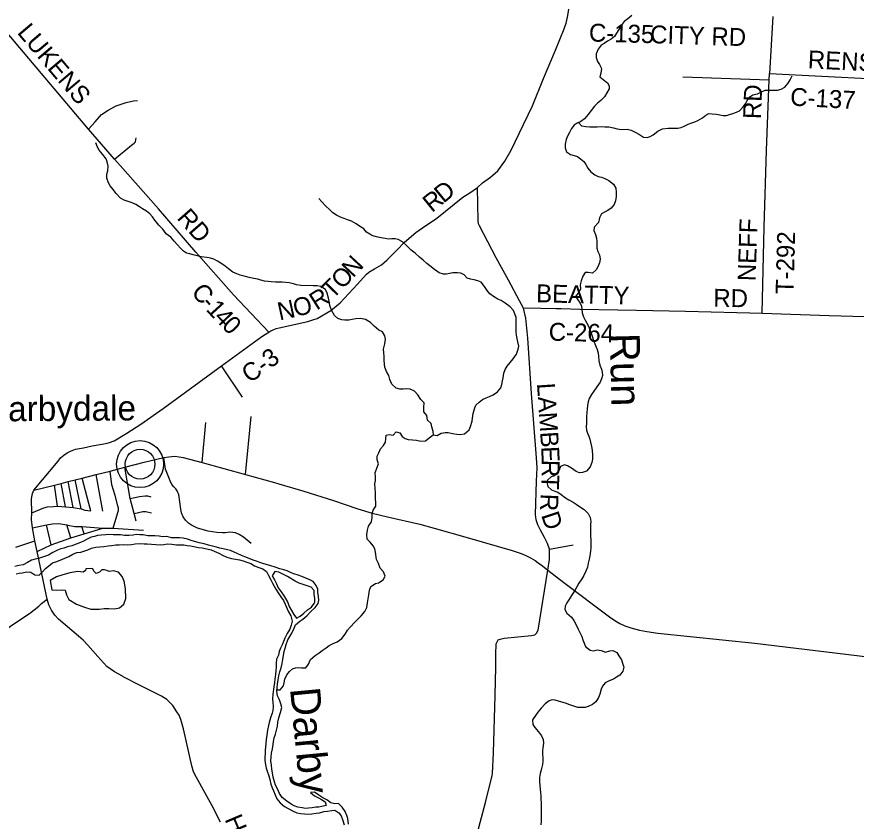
# Model space of a CAD drawing. Extents: x 114604 to 551442, y 316898 to 567001.
# Drawn here: x 152701 to 166736, y 341392 to 354850 of the extents above; entities that cross this region are included whole.
import ezdxf

# ---------------------------------------------------------------- set-up
doc = ezdxf.new("R2010")
doc.units = 0
for name, color, linetype in [('_CIVIL_CONSTRUCTION', 7, 'Continuous'), ('DV_X_County_Line', 7, 'Continuous'), ('GE_P_Alignment_1000_Cardinal_Points', 7, 'Continuous'), ('GE_P_Alignment_500_Bearings', 7, 'Continuous'), ('GE_X_Alignment', 7, 'Continuous'), ('MT_X_Edge_Line', 7, 'Continuous'), ('PM_P_Cells', 7, 'Continuous'), ('PM_P_CL_Double_Solid', 7, 'Continuous'), ('PM_P_Crosswalk', 7, 'Continuous'), ('PM_P_Stop_Line', 7, 'Continuous'), ('PM_X_Dotted_Line', 7, 'Continuous'), ('RD_P_GR_Rt', 7, 'Continuous')]:
    doc.layers.add(name, color=color, linetype=linetype)

msp = doc.modelspace()

# ---------------------------------------------------------------- linework, layer by layer
at = {"layer": '_CIVIL_CONSTRUCTION'}
msp.add_line((153001, 346082), (152964, 346298), dxfattribs=at)
for points in [[(152987, 346930), (153329, 347014), (153443, 347044), (153560, 347074), (153678, 347101), (153796, 347130), (154026, 347193), (154264, 347251), (154507, 347314), (154833, 347397)], [(154833, 347397), (155159, 347479), (155241, 347491), (155344, 347502), (155416, 347491), (155481, 347478), (155799, 347391), (156523, 347192), (157007, 347061), (157083, 347039)], [(157083, 347039), (157501, 346914), (157996, 346758), (158401, 346621), (158645, 346548), (158900, 346483), (159440, 346362), (159681, 346296), (160232, 346139), (160984, 345923), (161137, 345870), (161214, 345836), (161291, 345800), (161366, 345754), (161421, 345716), (161492, 345665), (161581, 345594)], [(152950, 346553), (152948, 346780), (152952, 346817), (152961, 346877), (152987, 346930)], [(152964, 346298), (152949, 346442), (152950, 346553)], [(152685, 345975), (152816, 346019), (153001, 346082)], [(161581, 345594), (161846, 345387), (162609, 344810), (162702, 344748), (162782, 344699), (162868, 344661), (162967, 344625), (163115, 344590), (163234, 344565), (163417, 344541), (165040, 344369), (166930, 344140), (170354, 343709), (170556, 343684), (170781, 343660)]]:
    msp.add_lwpolyline(points, dxfattribs=at)
at = {"layer": 'DV_X_County_Line'}
for points in [[(157733, 345272), (157705, 345336), (157655, 345400), (157599, 345433), (157531, 345457), (157465, 345485), (157405, 345509), (157331, 345533), (157277, 345556), (157223, 345580), (157165, 345598), (157101, 345616), (157019, 345644), (156947, 345667), (156893, 345681), (156831, 345697), (156767, 345721), (156709, 345741), (156655, 345762), (156585, 345790), (156513, 345818), (156457, 345840), (156387, 345871), (156335, 345891), (156275, 345919), (156223, 345935), (156151, 345951), (156097, 345963), (156041, 345978), (155973, 345992), (155905, 346012), (155831, 346032), (155751, 346051), (155697, 346065), (155631, 346085), (155553, 346111), (155481, 346127), (155421, 346136), (155351, 346136), (155285, 346134), (155211, 346156), (155139, 346152), (155079, 346159), (155009, 346165), (154957, 346165), (154891, 346169), (154811, 346185), (154760, 346186), (154698, 346188), (154644, 346180), (154572, 346170), (154504, 346174), (154436, 346181), (154376, 346185), (154310, 346185), (154240, 346189), (154188, 346185), (154112, 346179), (154050, 346172), (153998, 346154), (153946, 346142), (153888, 346118), (153815, 346080), (153765, 346056), (153691, 346025), (153623, 346001), (153549, 345981), (153489, 345963), (153435, 345947), (153383, 345927), (153304, 345890), (153230, 345846), (153162, 345822), (153112, 345806), (153062, 345788), (153010, 345776), (152944, 345759), (152878, 345721), (152809, 345679), (152733, 345669), (152667, 345651)], [(152689, 345531), (152739, 345541), (152789, 345549), (152871, 345565), (152937, 345560), (153005, 345516), (153073, 345506), (153131, 345562), (153180, 345620), (153230, 345662), (153298, 345715), (153352, 345731), (153426, 345759), (153504, 345793), (153573, 345823), (153639, 345861), (153703, 345886), (153771, 345894), (153823, 345908), (153889, 345934), (153951, 345962), (154023, 345978), (154091, 345985), (154157, 345991), (154226, 345997)], [(154226, 345997), (154282, 346003), (154358, 346017), (154410, 346016), (154478, 346020), (154544, 346018), (154620, 346024), (154682, 346032), (154750, 346037), (154828, 346035), (154882, 346031), (154952, 346029), (155024, 346021), (155096, 346014), (155160, 346022), (155223, 346034), (155295, 346028), (155369, 346018), (155445, 346017), (155495, 346015), (155549, 346003), (155603, 345997), (155661, 345989), (155737, 345972), (155803, 345966), (155877, 345950), (155949, 345934), (156003, 345910), (156081, 345875), (156139, 345843), (156215, 345811), (156291, 345789), (156355, 345777), (156423, 345764), (156487, 345750), (156549, 345726), (156615, 345704), (156677, 345663), (156749, 345635), (156813, 345615), (156877, 345571), (156911, 345503), (156941, 345441), (156979, 345374), (157004, 345322), (157030, 345272), (157080, 345198), (157116, 345148), (157160, 345084), (157188, 345023), (157222, 344945), (157246, 344893), (157282, 344831), (157303, 344741), (157291, 344673), (157267, 344603), (157223, 344531), (157185, 344457), (157158, 344397), (157136, 344345), (157112, 344289), (157090, 344233), (157074, 344169), (157046, 344105), (157037, 344035), (157035, 343973), (157031, 343909), (157025, 343845), (157015, 343769), (157009, 343715), (156998, 343643), (156980, 343517), (156974, 343441), (156980, 343376), (156988, 343314), (156981, 343243), (156971, 343198), (156943, 343124), (156921, 343046), (156909, 342992), (156893, 342916), (156880, 342834), (156872, 342762), (156864, 342686), (156856, 342582), (156852, 342518), (156850, 342468), (156849, 342414), (156857, 342334), (156871, 342278), (156889, 342228), (156913, 342151), (156929, 342089), (156949, 342013), (156972, 341951), (156994, 341899), (157020, 341835), (157048, 341767), (157102, 341698), (157176, 341640), (157248, 341598)], [(157013, 345570), (156973, 345496), (157007, 345428), (157041, 345362), (157070, 345298), (157120, 345232), (157160, 345174), (157196, 345119), (157234, 345051), (157256, 344983), (157292, 344915), (157332, 344849), (157376, 344787), (157440, 344825), (157500, 344872), (157564, 344930), (157628, 344974), (157674, 345032)], [(157674, 345032), (157684, 345056), (157685, 345124), (157675, 345186), (157671, 345252), (157623, 345306), (157557, 345331), (157491, 345351), (157425, 345373), (157357, 345409), (157225, 345486), (157149, 345526), (157083, 345560), (157013, 345570)], [(158248, 341343), (158238, 341437), (158218, 341489), (158193, 341555), (158141, 341627), (158081, 341688), (158017, 341684), (157951, 341702), (157887, 341752), (157817, 341781), (157751, 341827), (157679, 341881), (157609, 341875), (157679, 341819), (157745, 341783), (157797, 341755), (157859, 341718), (157873, 341656), (157804, 341636), (157752, 341629), (157702, 341627), (157642, 341615), (157580, 341609), (157526, 341605), (157474, 341615), (157398, 341630), (157340, 341648), (157286, 341678), (157216, 341726), (157136, 341790), (157092, 341855), (157058, 341933), (157029, 341997), (157009, 342053), (156989, 342131), (156979, 342199), (156967, 342265), (156959, 342329), (156951, 342402), (156954, 342466), (156958, 342530), (156976, 342606), (156988, 342676), (156992, 342726), (157006, 342790), (157029, 342850), (157045, 342916), (157059, 342982), (157067, 343048), (157083, 343120), (157112, 343212), (157130, 343292), (157114, 343356), (157092, 343424), (157062, 343492), (157051, 343566), (157053, 343632), (157059, 343687), (157069, 343755), (157085, 343823), (157101, 343893), (157121, 343961), (157136, 344029), (157148, 344099), (157162, 344169), (157174, 344231), (157188, 344289), (157206, 344351), (157235, 344427), (157265, 344481), (157301, 344541), (157339, 344621), (157361, 344679), (157433, 344740), (157486, 344772), (157548, 344826), (157620, 344900), (157688, 344966), (157738, 345036), (157751, 345088), (157747, 345152), (157735, 345222), (157733, 345272)], [(157248, 341598), (157320, 341560), (157384, 341533), (157446, 341521), (157510, 341515), (157560, 341513), (157632, 341517), (157706, 341525), (157760, 341534), (157834, 341556), (157898, 341560), (157968, 341574), (158020, 341576), (158084, 341534), (158122, 341481), (158152, 341407), (158172, 341333)]]:
    msp.add_lwpolyline(points, dxfattribs=at)
at = {"layer": 'GE_P_Alignment_1000_Cardinal_Points'}
for p, q in [((163838, 353844), (165281, 353796)), ((156474, 348489), (156126, 349009)), ((156523, 347192), (156619, 348163)), ((155799, 347391), (155859, 348064)), ((154142, 346577), (154026, 347193)), ((153383, 346661), (153329, 347014)), ((153515, 346653), (153443, 347044)), ((153645, 346641), (153560, 347074)), ((153776, 346617), (153678, 347101)), ((154662, 346539), (154806, 346573)), ((153273, 346016), (153199, 346351)), ((153605, 346135), (153540, 346352)), ((153830, 346198), (153788, 346325)), ((161607, 345941), (162006, 346018))]:
    msp.add_line(p, q, dxfattribs=at)
for points in [[(165163, 349894), (165199, 351333), (165237, 352613), (165281, 353796), (165285, 353903)], [(153900, 352972), (154010, 353094), (154118, 353214), (154226, 353286), (154364, 353360), (154527, 353418), (154653, 353442), (154717, 353450)], [(154336, 352471), (154619, 352700), (154663, 352736), (154685, 352756), (154697, 352823)], [(156618, 346037), (156494, 346143), (156418, 346191), (156357, 346217), (156313, 346225), (156263, 346227), (156193, 346219), (156139, 346217), (156043, 346221), (155901, 346243), (155721, 346297), (155623, 346347), (155571, 346379), (155523, 346426), (155481, 346484), (155456, 346550), (155446, 346614), (155428, 346734), (155410, 346856), (155396, 346892), (155380, 346922), (155358, 346954), (155324, 346984), (155294, 347024), (155264, 347085), (155187, 347281), (155159, 347479)], [(154314, 346293), (154392, 346559), (154400, 346593), (154400, 346632), (154390, 346666), (154345, 346842), (154291, 347022), (154264, 347251)], [(154696, 346413), (154662, 346539), (154598, 346792), (154507, 347314)], [(153939, 346585), (153905, 346710), (153796, 347130)], [(154598, 346792), (154754, 346822), (154848, 346836), (154884, 346836), (154942, 346818)], [(152950, 346553), (153151, 346633), (153215, 346653), (153313, 346659), (153383, 346661), (153515, 346653), (153645, 346641), (153776, 346617), (153841, 346597), (153939, 346585)], [(154806, 346573), (154816, 346576), (154860, 346572), (154952, 346550)], [(152964, 346298), (153199, 346351), (153295, 346367), (153405, 346373), (153540, 346352), (153556, 346345), (153670, 346325), (153788, 346325), (154140, 346293), (154314, 346293), (154822, 346261)], [(153044, 345907), (153273, 346016), (153605, 346135), (153830, 346198), (154140, 346293)]]:
    msp.add_lwpolyline(points, dxfattribs=at)
at = {"layer": 'GE_P_Alignment_500_Bearings'}
for p, q in [((165345, 354855), (165285, 353903)), ((153001, 346082), (152964, 346298))]:
    msp.add_line(p, q, dxfattribs=at)
for points in [[(156916, 349576), (156322, 350196), (155695, 350914), (155069, 351636), (154476, 352310), (154336, 352471), (153900, 352972), (152020, 355197), (151780, 355470), (151703, 355576)], [(160403, 351997), (160487, 352071), (160621, 352165), (160745, 352275), (160859, 352435), (160968, 352619), (161100, 352900), (161324, 353358), (161506, 353819), (161706, 354289), (161856, 354646), (161884, 354744), (161907, 354845), (161939, 355007)], [(165285, 353903), (171410, 353589), (172060, 353554), (172093, 353569), (172106, 353604), (172140, 354125), (172151, 354163), (172179, 354179)], [(152987, 346930), (153390, 347416), (153431, 347469), (153486, 347516), (153541, 347553), (153598, 347584), (153682, 347614), (153818, 347641), (153962, 347670), (154156, 347704), (154212, 347716), (154252, 347726), (154329, 347755), (154540, 347884), (154777, 348034), (155148, 348295), (156126, 349009), (156800, 349503), (156859, 349543), (156916, 349576), (156949, 349596), (156988, 349613), (157039, 349633), (157087, 349647), (157567, 349750), (157653, 349778), (157721, 349802), (157951, 349934), (158105, 350066), (158399, 350376), (158543, 350540), (158588, 350578), (158680, 350632), (158800, 350702), (158890, 350780), (159058, 350948), (159186, 351077), (159374, 351239), (159486, 351319), (159726, 351481), (160159, 351833), (160275, 351903), (160403, 351997)], [(161581, 345594), (161606, 345768), (161609, 345863), (161607, 345941), (161572, 346036), (161524, 346139), (161458, 346264), (161414, 346348), (161386, 346436), (161375, 346521), (161392, 347083), (161401, 347307), (161389, 347471), (161308, 348550), (161245, 349475), (161215, 349806), (161176, 349974), (161107, 350096), (160921, 350442), (160714, 350818), (160435, 351353), (160423, 351387), (160418, 351435), (160403, 351997)], [(161176, 349974), (161206, 349979), (161721, 349970), (161805, 349968)], [(161805, 349968), (162121, 349961), (162752, 349947), (163062, 349941)], [(163062, 349941), (163880, 349924), (164742, 349902), (164959, 349896), (165163, 349894)], [(165163, 349894), (166286, 349855), (167279, 349825), (168631, 349785), (169499, 349762), (169890, 349748), (170770, 349721), (171512, 349704), (172003, 349694), (172034, 349694)], [(152950, 346553), (152948, 346780), (152952, 346817), (152961, 346877), (152987, 346930)], [(152964, 346298), (152949, 346442), (152950, 346553)], [(153184, 345213), (153044, 345907), (153001, 346082)], [(160398, 341183), (160542, 341726), (160648, 342157), (160654, 342191), (160674, 342539), (160700, 343493), (160712, 343970), (160708, 344184), (160714, 344360), (160732, 344396), (160750, 344426), (160784, 344440), (160848, 344452), (161307, 344498), (161364, 344513), (161393, 344538), (161420, 344591), (161581, 345594)], [(154481, 343809), (154467, 343817), (154335, 343890), (154204, 343981), (154056, 344146), (153890, 344338), (153811, 344420), (153733, 344488), (153399, 344773), (153335, 344842), (153282, 344925), (153238, 345014), (153206, 345106), (153184, 345213)], [(152177, 344211), (152186, 344230), (152274, 344368), (152428, 344516), (152602, 344660), (152912, 344870), (153068, 344988), (153114, 345036), (153206, 345106)], [(156105, 341379), (155970, 341648), (155706, 342124), (155656, 342220), (155627, 342321), (155488, 342937), (155442, 343094), (155414, 343165), (155379, 343225), (155308, 343329), (155251, 343392), (155209, 343430), (155120, 343487), (154764, 343662), (154481, 343809)]]:
    msp.add_lwpolyline(points, dxfattribs=at)
at = {"layer": 'GE_X_Alignment'}
for radius in [393, 249]:
    msp.add_circle((154762, 347366), radius, dxfattribs=at)
at = {"layer": 'MT_X_Edge_Line'}
for points in [[(153857, 345617), (153851, 345585), (153812, 345559), (153722, 345568), (153588, 345547), (153453, 345510), (153365, 345483), (153258, 345418), (153285, 345261), (153359, 345257), (153457, 345264), (153509, 345259), (153533, 345177), (153570, 345099), (153700, 345021), (153832, 344974), (153941, 344939), (154078, 344938), (154164, 344949), (154242, 344950), (154332, 344946), (154416, 344961), (154489, 345022), (154526, 345118), (154521, 345281), (154494, 345407), (154465, 345487), (154401, 345558), (154317, 345579), (154245, 345568), (154209, 345586), (154169, 345600), (154121, 345599), (154081, 345559), (154028, 345537), (153995, 345572), (153965, 345622)], [(153965, 345622), (153857, 345617)]]:
    msp.add_lwpolyline(points, dxfattribs=at)
at = {"layer": 'PM_P_Cells'}
for points in [[(162982, 354874), (162915, 354816), (162855, 354771), (162808, 354703), (162769, 354635), (162731, 354577), (162694, 354523), (162638, 354474), (162579, 354442), (162523, 354405), (162473, 354373), (162424, 354307), (162391, 354233), (162387, 354167), (162410, 354101), (162446, 354051), (162475, 353984), (162465, 353906), (162452, 353844), (162508, 353802), (162580, 353743), (162603, 353693), (162603, 353643), (162566, 353577), (162526, 353511), (162465, 353451), (162413, 353406), (162362, 353354), (162303, 353280), (162249, 353209), (162194, 353145), (162130, 353098), (162071, 353072), (162021, 353036), (161976, 352983), (161940, 352915), (161909, 352853), (161889, 352797), (161868, 352721), (161868, 352657), (161891, 352591), (161961, 352546), (162023, 352531), (162077, 352513), (162128, 352474), (162182, 352428), (162214, 352377), (162249, 352315), (162297, 352256), (162367, 352204), (162422, 352181), (162478, 352167), (162532, 352146), (162602, 352112), (162678, 352051), (162715, 351982), (162723, 351918), (162722, 351844), (162711, 351772), (162689, 351710), (162640, 351648), (162586, 351609), (162536, 351585), (162479, 351554), (162445, 351484), (162426, 351406), (162357, 351330), (162351, 351274), (162378, 351206), (162392, 351145), (162397, 351093), (162397, 351035), (162400, 350977), (162418, 350925), (162442, 350867), (162455, 350798), (162442, 350732), (162424, 350680), (162391, 350616), (162329, 350563), (162255, 350574), (162203, 350570), (162164, 350510), (162137, 350432), (162123, 350368), (162124, 350298), (162104, 350246), (162045, 350173), (162081, 350114), (162122, 350060), (162142, 350007), (162146, 349957), (162155, 349897), (162177, 349829), (162206, 349776), (162234, 349726)], [(162095, 353083), (162141, 353027), (162213, 353013), (162283, 353010), (162341, 353008), (162403, 353009), (162475, 353012), (162533, 353010), (162600, 353007), (162676, 352995), (162739, 352976), (162807, 352963), (162908, 352971), (162974, 352952), (163043, 352921), (163111, 352881), (163177, 352834), (163239, 352829), (163289, 352845), (163344, 352877), (163420, 352938), (163497, 352976), (163591, 352985), (163641, 352986), (163693, 352986), (163753, 352989), (163809, 352999), (163862, 353020), (163928, 353052), (163986, 353077), (164036, 353095), (164087, 353117), (164165, 353160), (164222, 353202), (164272, 353231), (164326, 353229), (164398, 353220), (164458, 353210), (164512, 353197), (164566, 353197), (164616, 353216), (164673, 353234), (164735, 353253), (164787, 353279), (164848, 353341), (164886, 353396), (164913, 353452), (164957, 353512), (165010, 353544), (165088, 353559), (165142, 353589), (165213, 353620), (165287, 353623), (165367, 353625), (165423, 353622), (165483, 353638), (165545, 353671), (165600, 353741), (165631, 353793), (165667, 353863)], [(154497, 351785), (154433, 351816), (154364, 351895), (154314, 351959), (154263, 352022), (154235, 352074), (154204, 352149), (154208, 352217), (154223, 352275), (154227, 352351), (154214, 352421), (154194, 352475), (154133, 352554), (154077, 352621), (154048, 352671), (154022, 352740)], [(159668, 347854), (159663, 347911), (159643, 347989), (159630, 348047), (159566, 348100), (159557, 348182), (159507, 348239), (159504, 348315), (159511, 348389), (159455, 348448), (159404, 348528), (159350, 348587), (159276, 348623), (159216, 348624), (159160, 348622), (159106, 348623), (159044, 348636), (158974, 348704), (158941, 348781), (158919, 348847), (158882, 348917), (158855, 348988), (158849, 349038), (158846, 349112), (158844, 349174), (158837, 349230), (158831, 349291), (158854, 349377), (158864, 349457), (158853, 349513), (158815, 349577), (158752, 349608), (158674, 349675), (158614, 349737), (158529, 349784), (158447, 349805), (158369, 349796), (158306, 349784), (158254, 349777), (158188, 349775), (158136, 349782), (158068, 349800), (158014, 349851), (157963, 349941), (157936, 350018), (157924, 350090), (157913, 350144), (157891, 350227), (157864, 350289), (157784, 350336), (157722, 350348), (157654, 350351), (157450, 350353), (157380, 350367), (157326, 350380), (157256, 350402), (157198, 350407), (157140, 350410), (157088, 350412), (157024, 350413), (156954, 350417), (156903, 350420), (156845, 350428), (156783, 350445), (156730, 350459), (156664, 350474), (156588, 350491), (156504, 350511), (156438, 350528), (156378, 350548), (156314, 350577), (156242, 350634), (156184, 350676), (156111, 350729), (156059, 350762), (155993, 350798), (155941, 350811), (155881, 350821), (155785, 350836), (155717, 350853), (155651, 350869), (155593, 350886), (155541, 350898), (155490, 350931), (155436, 350980), (155388, 351036), (155331, 351097), (155275, 351161), (155201, 351220), (155142, 351295), (155076, 351365), (155009, 351448), (154969, 351503), (154926, 351555), (154870, 351598), (154804, 351638), (154751, 351673), (154693, 351708), (154631, 351738), (154563, 351761), (154497, 351785)], [(160332, 348216), (160353, 348290), (160378, 348351), (160430, 348405), (160485, 348445), (160547, 348474), (160607, 348500), (160667, 348527), (160740, 348575), (160793, 348644), (160813, 348700), (160824, 348758), (160832, 348810), (160847, 348888), (160867, 348950), (160900, 349004), (160948, 349066), (161001, 349128), (161054, 349207), (161084, 349289), (161093, 349341), (161077, 349411), (161068, 349468), (161056, 349526), (161051, 349578), (161052, 349762), (161049, 349818), (161031, 349879), (161004, 349937), (160948, 349996), (160866, 350061), (160799, 350103), (160745, 350128), (160673, 350170), (160611, 350215), (160566, 350270), (160522, 350338), (160465, 350409), (160409, 350433), (160349, 350448), (160289, 350458), (160233, 350477), (160183, 350533), (160128, 350562), (160072, 350568), (159993, 350565), (159935, 350554), (159883, 350546), (159833, 350542), (159765, 350567), (159687, 350624), (159608, 350683), (159556, 350725), (159496, 350778), (159435, 350826), (159361, 350897), (159297, 350948), (159224, 351019), (159148, 351083), (159079, 351126), (159025, 351137), (158971, 351133), (158910, 351132), (158858, 351140), (158794, 351153), (158716, 351167), (158656, 351186), (158603, 351212), (158547, 351247), (158501, 351301), (158447, 351338), (158374, 351389), (158296, 351429), (158232, 351454), (158174, 351475), (158122, 351495), (158046, 351534), (157987, 351572), (157937, 351623), (157863, 351688), (157800, 351756), (157750, 351811)], [(162234, 349726), (162261, 349672), (162283, 349617), (162307, 349559), (162322, 349505), (162344, 349433), (162375, 349352), (162404, 349282), (162422, 349225), (162429, 349171), (162435, 349095), (162448, 349023), (162476, 348956), (162489, 348904), (162493, 348850), (162480, 348794), (162454, 348738), (162397, 348661), (162347, 348587), (162308, 348529), (162271, 348465), (162255, 348407), (162246, 348345), (162238, 348285), (162233, 348231), (162229, 348165), (162226, 348103), (162226, 348051), (162221, 347989), (162225, 347937), (162245, 347886), (162268, 347834), (162284, 347782), (162295, 347732), (162311, 347661), (162320, 347599), (162328, 347517), (162325, 347451), (162315, 347391), (162290, 347323), (162227, 347251), (162161, 347226), (162109, 347220), (162053, 347241), (161975, 347300), (161909, 347336), (161858, 347355), (161791, 347327), (161767, 347267), (161744, 347215), (161690, 347170), (161638, 347154), (161577, 347099), (161571, 347043), (161582, 346992), (161644, 346934), (161698, 346915), (161750, 346895), (161801, 346856), (161873, 346804), (161933, 346771), (162001, 346732), (162054, 346698), (162126, 346649), (162190, 346608), (162257, 346540), (162287, 346473), (162298, 346407), (162296, 346355), (162293, 346281), (162293, 346227), (162294, 346157), (162298, 346106), (162299, 346034), (162299, 345966), (162292, 345908), (162280, 345834), (162269, 345776), (162257, 345710), (162242, 345644), (162217, 345578), (162181, 345504), (162148, 345446), (162097, 345373), (162065, 345311), (162032, 345251), (161978, 345169), (161943, 345110), (161900, 345048), (161868, 344988), (161864, 344936), (161897, 344872), (161975, 344805), (162016, 344750), (162060, 344664), (162089, 344605), (162148, 344485), (162168, 344428), (162189, 344370), (162211, 344318), (162288, 344255)], [(157051, 343590), (157105, 343589), (157158, 343656), (157172, 343708), (157185, 343768), (157215, 343840), (157258, 343898), (157308, 343941), (157359, 343961), (157411, 343963), (157463, 343958), (157531, 343960), (157581, 344021), (157610, 344097), (157689, 344163), (157755, 344210), (157806, 344250), (157874, 344295), (157924, 344331), (157991, 344368), (158059, 344396), (158136, 344447), (158190, 344523), (158233, 344587), (158280, 344644), (158346, 344718), (158397, 344766), (158459, 344827), (158520, 344903), (158553, 344967), (158567, 345047), (158576, 345111), (158587, 345181), (158599, 345259), (158620, 345321), (158696, 345368), (158748, 345378), (158825, 345429), (158862, 345493), (158832, 345563), (158775, 345626), (158749, 345704), (158716, 345769), (158701, 345893), (158685, 345947), (158657, 345998), (158610, 346058), (158562, 346109), (158553, 346191), (158565, 346259), (158584, 346329), (158631, 346401), (158645, 346475), (158644, 346537), (158658, 346595), (158705, 346663), (158704, 346729), (158698, 346781), (158700, 346839), (158701, 346893), (158691, 346961), (158688, 347036), (158697, 347092), (158699, 347152), (158692, 347220), (158720, 347296), (158749, 347370), (158726, 347438), (158726, 347498), (158753, 347556), (158781, 347620), (158832, 347677), (158868, 347733), (158871, 347787), (158877, 347851), (158929, 347863), (158995, 347852), (159044, 347908), (159106, 347892), (159143, 347829), (159195, 347793), (159247, 347778), (159317, 347773), (159385, 347765), (159457, 347752), (159533, 347754), (159594, 347805), (159662, 347855), (159730, 347848), (159795, 347884), (159863, 347897), (159915, 347897), (159987, 347880), (160061, 347869), (160117, 347863), (160189, 347872), (160266, 347942), (160288, 347994), (160315, 348083), (160322, 348137), (160332, 348216)], [(162288, 344255), (162340, 344242), (162407, 344262), (162471, 344249), (162543, 344223), (162617, 344242), (162669, 344246), (162733, 344213), (162768, 344161), (162810, 344092), (162835, 344022), (162849, 343972), (162834, 343900), (162782, 343836), (162729, 343800), (162679, 343769), (162607, 343743), (162538, 343706), (162496, 343654), (162471, 343602), (162449, 343520), (162426, 343462), (162381, 343388), (162329, 343347), (162257, 343311), (162202, 343296), (162140, 343292), (162084, 343297), (161948, 343338), (161876, 343365), (161813, 343385), (161757, 343402), (161705, 343416), (161653, 343425), (161602, 343405), (161538, 343356), (161471, 343284), (161415, 343218), (161372, 343159), (161323, 343089), (161331, 343009), (161364, 342958), (161422, 342888), (161473, 342819), (161501, 342757), (161506, 342699), (161496, 342621), (161491, 342567), (161493, 342512), (161496, 342448), (161498, 342398), (161493, 342340), (161469, 342250), (161450, 342192), (161442, 342126), (161441, 342058), (161444, 341994), (161454, 341924), (161459, 341871), (161461, 341817), (161463, 341761), (161466, 341701), (161470, 341647), (161471, 341593), (161471, 341527), (161468, 341464), (161467, 341392), (161463, 341334)]]:
    msp.add_lwpolyline(points, dxfattribs=at)
at = {"layer": 'PM_X_Dotted_Line'}
msp.add_line((154762, 347366), (154762, 347366), dxfattribs=at)

# ---------------------------------------------------------------- texts
at = {"layer": '_CIVIL_CONSTRUCTION'}
msp.add_text('Darbydale', height=417, rotation=0.4122, dxfattribs=at).set_placement((152154, 348080))
at = {"layer": 'PM_P_CL_Double_Solid'}
for s, rotation, p in [('LUKENS', 310.24, (152695, 354582)), ('C-135', 358.4849, (162264, 354437)), ('CITY RD', 358.177, (163287, 354409)), ('RENSCH', 357.0977, (165922, 353989)), ('C-137', 356.836, (165627, 353366)), ('D', 39.4399, (159835, 351721)), ('R', 38.9576, (159641, 351565)), ('RD', 311.227, (155365, 351478)), ('N', 47.0924, (158325, 350471)), ('O', 46.933, (158144, 350277)), ('T', 45.6534, (157982, 350112)), ('C', 310.804, (155604, 350234)), ('BEATTY', 358.5091, (161381, 350076)), ('R', 32.2915, (157714, 349932)), ('RD', 358.9318, (164345, 350000)), ('-', 311.3306, (155767, 350045)), ('1', 312.3549, (155852, 349948)), ('N', 12.2962, (157095, 349769)), ('O', 14.0108, (157362, 349827)), ('4', 313.6071, (155982, 349806)), ('0', 314.5025, (156113, 349669)), ('C-264', 358.4802, (161592, 349433)), ('C-3', 36.002, (156597, 348711)), ('L', 273.7398, (161398, 348715)), ('A', 273.7358, (161413, 348491)), ('M', 273.7397, (161430, 348228)), ('B', 273.6966, (161451, 347903)), ('E', 272.7873, (161467, 347658)), ('R', 269.2609, (161478, 347439)), ('T', 267.4025, (161475, 347195)), ('R', 267.7083, (161460, 346876)), ('D', 288.0665, (161466, 346515)), ('H', 292.9118, (156171, 341426))]:
    msp.add_text(s, height=300, rotation=rotation, dxfattribs=at).set_placement(p)
at = {"layer": 'PM_P_Crosswalk'}
for s, rotation, p in [('RD', 87.9438, (165144, 353135)), ('NEFF', 88.1669, (165054, 350424)), ('T-292', 88.4472, (165688, 350208))]:
    msp.add_text(s, height=300, rotation=rotation, dxfattribs=at).set_placement(p)
at = {"layer": 'PM_P_Stop_Line'}
msp.add_text('Run', height=500, rotation=271.3826, dxfattribs=at).set_placement((162616, 349554))
at = {"layer": 'RD_P_GR_Rt'}
msp.add_text('Darby', height=500, rotation=275.4131, dxfattribs=at).set_placement((157269, 343611))

doc.saveas('drawing.dxf')
